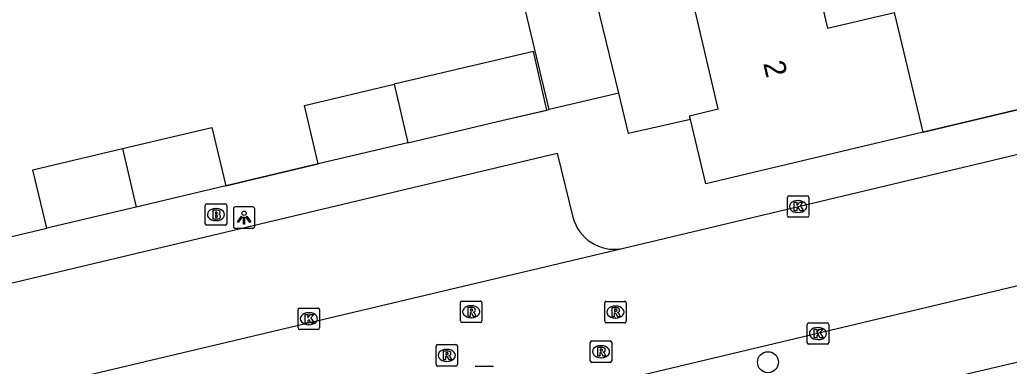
# Model space of a CAD drawing. Extents: x 158038 to 159242, y 380133 to 381214.
# Drawn here: x 158594.98 to 158641.12, y 380505 to 380521.13 of the extents above; entities that cross this region are included whole.
import ezdxf

# ---------------------------------------------------------------- set-up
doc = ezdxf.new("R2010")
doc.units = 0
for name, color, linetype in [('IMGEO_Boom', 7, 'Continuous'), ('IMGEO_Brandkraan', 7, 'Continuous'), ('IMGEO_Hek', 7, 'Continuous'), ('IMGEO_Kolk', 7, 'Continuous'), ('IMGEO_Lichtpunt', 7, 'Continuous'), ('IMGEO_Muur', 7, 'Continuous'), ('IMGEO_Pand', 7, 'Continuous'), ('IMGEO_Pand_nummerreeks', 7, 'Continuous'), ('IMGEO_Rijbaan_lokaal_open', 7, 'Continuous'), ('IMGEO_Rioolput', 7, 'Continuous'), ('IMGEO_Voetpad_open', 7, 'Continuous')]:
    doc.layers.add(name, color=color, linetype=linetype)

msp = doc.modelspace()

# ---------------------------------------------------------------- linework, layer by layer
at = {"layer": 'IMGEO_Boom'}
msp.add_circle((158629.869, 380505.187), 0.489, dxfattribs=at)
at = {"layer": 'IMGEO_Brandkraan'}
for p, q in [((158603.628, 380511.636), (158603.628, 380512.488)), ((158603.703, 380512.562), (158604.555, 380512.562)), ((158604.629, 380512.488), (158604.629, 380511.636)), ((158604.116, 380512.342), (158604.141, 380512.342)), ((158604.555, 380511.562), (158603.703, 380511.562)), ((158604.139, 380511.782), (158604.114, 380511.782))]:
    msp.add_line(p, q, dxfattribs=at)
for points in [[(158603.628, 380511.636), (158603.628, 380512.488)], [(158603.703, 380512.562), (158604.555, 380512.562)], [(158604.629, 380512.488), (158604.629, 380511.636)], [(158603.976, 380512.262), (158603.976, 380511.862), (158604.189, 380511.862)], [(158604.207, 380512.262), (158603.976, 380512.262)], [(158604.155, 380512.181), (158604.101, 380512.181), (158604.101, 380512.105)], [(158604.101, 380512.105), (158604.154, 380512.105)], [(158604.163, 380512.029), (158604.101, 380512.029), (158604.101, 380511.948)], [(158604.555, 380511.562), (158603.703, 380511.562)], [(158604.101, 380511.948), (158604.163, 380511.948)]]:
    msp.add_lwpolyline(points, dxfattribs=at)
for centre, radius, start, end in [((158603.705, 380512.486), 0.0765, 91.552, 178.448), ((158603.705, 380512.486), 0.0765, 91.552, 178.448), ((158604.553, 380512.486), 0.0765, 1.552, 88.448), ((158604.553, 380512.486), 0.0765, 1.552, 88.448), ((158604.156, 380512.143), 0.0379, 267.8285, 90.9355), ((158604.164, 380511.988), 0.0404, 269.8759, 90.5077), ((158604.211, 380512.117), 0.145, 59.4692, 91.5367), ((158604.236, 380512.164), 0.0922, 285.5137, 58.1501), ((158604.241, 380511.972), 0.105, 301.3115, 78.989), ((158603.705, 380511.638), 0.0765, 181.552, 268.448), ((158603.705, 380511.638), 0.0765, 181.552, 268.448), ((158604.195, 380512.113), 0.251, 268.6676, 293.5347), ((158604.553, 380511.638), 0.0765, 271.552, 358.448), ((158604.553, 380511.638), 0.0765, 271.552, 358.448)]:
    msp.add_arc(centre, radius, start, end, dxfattribs=at)
for centre, major_axis, ratio, start_param, end_param in [((158604.115, 380512.062), (-0.387, 0.002), 0.722429, 4.712389, 7.853982), ((158604.14, 380512.062), (-0.39, 0.002), 0.717154, 1.570796, 4.712389)]:
    msp.add_ellipse(centre, major_axis=major_axis, ratio=ratio, start_param=start_param, end_param=end_param, dxfattribs=at)
at = {"layer": 'IMGEO_Hek'}
for points in [[(158637.101, 380515.894), (158657.23, 380520.681)], [(158608.894, 380514.423), (158604.583, 380513.396)]]:
    msp.add_lwpolyline(points, dxfattribs=at)
at = {"layer": 'IMGEO_Kolk'}
for p, q in [((158630.848, 380512.937), (158631.7, 380512.937)), ((158630.773, 380512.011), (158630.773, 380512.863)), ((158631.261, 380512.717), (158631.286, 380512.717)), ((158631.774, 380512.863), (158631.774, 380512.011)), ((158631.284, 380512.157), (158631.259, 380512.157)), ((158631.7, 380511.937), (158630.848, 380511.937)), ((158607.961, 380506.784), (158607.961, 380507.636)), ((158608.036, 380507.71), (158608.888, 380507.71)), ((158608.449, 380507.49), (158608.474, 380507.49)), ((158608.962, 380507.636), (158608.962, 380506.784)), ((158631.698, 380506.095), (158631.698, 380506.947)), ((158631.773, 380507.021), (158632.625, 380507.021)), ((158632.699, 380506.947), (158632.699, 380506.095)), ((158608.888, 380506.71), (158608.036, 380506.71)), ((158608.472, 380506.93), (158608.447, 380506.93)), ((158632.186, 380506.801), (158632.211, 380506.801)), ((158632.625, 380506.021), (158631.773, 380506.021)), ((158632.209, 380506.241), (158632.184, 380506.241))]:
    msp.add_line(p, q, dxfattribs=at)
for points in [[(158630.848, 380512.937), (158631.7, 380512.937)], [(158630.773, 380512.011), (158630.773, 380512.863)], [(158631.094, 380512.637), (158631.217, 380512.637), (158631.217, 380512.486), (158631.347, 380512.637), (158631.511, 380512.637), (158631.365, 380512.486), (158631.518, 380512.237), (158631.366, 380512.237), (158631.281, 380512.401), (158631.217, 380512.334), (158631.217, 380512.237), (158631.094, 380512.237), (158631.094, 380512.637)], [(158631.774, 380512.863), (158631.774, 380512.011)], [(158631.7, 380511.937), (158630.848, 380511.937)], [(158607.961, 380506.784), (158607.961, 380507.636)], [(158608.036, 380507.71), (158608.888, 380507.71)], [(158608.282, 380507.41), (158608.405, 380507.41), (158608.405, 380507.259), (158608.535, 380507.41), (158608.699, 380507.41), (158608.553, 380507.259), (158608.706, 380507.01), (158608.554, 380507.01), (158608.469, 380507.174), (158608.405, 380507.107), (158608.405, 380507.01), (158608.282, 380507.01), (158608.282, 380507.41)], [(158608.962, 380507.636), (158608.962, 380506.784)], [(158631.698, 380506.095), (158631.698, 380506.947)], [(158631.773, 380507.021), (158632.625, 380507.021)], [(158632.699, 380506.947), (158632.699, 380506.095)], [(158608.888, 380506.71), (158608.036, 380506.71)], [(158632.019, 380506.721), (158632.142, 380506.721), (158632.142, 380506.57), (158632.272, 380506.721), (158632.436, 380506.721), (158632.29, 380506.57), (158632.443, 380506.321), (158632.291, 380506.321), (158632.206, 380506.485), (158632.142, 380506.418), (158632.142, 380506.321), (158632.019, 380506.321), (158632.019, 380506.721)], [(158632.625, 380506.021), (158631.773, 380506.021)]]:
    msp.add_lwpolyline(points, dxfattribs=at)
for centre, start, end in [((158630.85, 380512.861), 91.552, 178.448), ((158630.85, 380512.861), 91.552, 178.448), ((158631.698, 380512.861), 1.552, 88.448), ((158631.698, 380512.861), 1.552, 88.448), ((158630.85, 380512.013), 181.552, 268.448), ((158630.85, 380512.013), 181.552, 268.448), ((158631.698, 380512.013), 271.552, 358.448), ((158631.698, 380512.013), 271.552, 358.448), ((158608.038, 380507.634), 91.552, 178.448), ((158608.038, 380507.634), 91.552, 178.448), ((158608.886, 380507.634), 1.552, 88.448), ((158608.886, 380507.634), 1.552, 88.448), ((158631.775, 380506.945), 91.552, 178.448), ((158631.775, 380506.945), 91.552, 178.448), ((158632.623, 380506.945), 1.552, 88.448), ((158632.623, 380506.945), 1.552, 88.448), ((158608.038, 380506.786), 181.552, 268.448), ((158608.038, 380506.786), 181.552, 268.448), ((158608.886, 380506.786), 271.552, 358.448), ((158608.886, 380506.786), 271.552, 358.448), ((158631.775, 380506.097), 181.552, 268.448), ((158631.775, 380506.097), 181.552, 268.448), ((158632.623, 380506.097), 271.552, 358.448), ((158632.623, 380506.097), 271.552, 358.448)]:
    msp.add_arc(centre, 0.0765, start, end, dxfattribs=at)
for centre, major_axis, ratio, start_param, end_param in [((158631.26, 380512.437), (-0.387, 0.002), 0.722429, 4.712389, 7.853982), ((158631.285, 380512.437), (-0.39, 0.002), 0.717154, 1.570796, 4.712389), ((158608.448, 380507.21), (-0.387, 0.002), 0.722429, 4.712389, 7.853982), ((158608.473, 380507.21), (-0.39, 0.002), 0.717154, 1.570796, 4.712389), ((158632.185, 380506.521), (-0.387, 0.002), 0.722429, 4.712389, 7.853982), ((158632.21, 380506.521), (-0.39, 0.002), 0.717154, 1.570796, 4.712389)]:
    msp.add_ellipse(centre, major_axis=major_axis, ratio=ratio, start_param=start_param, end_param=end_param, dxfattribs=at)
at = {"layer": 'IMGEO_Lichtpunt'}
for p, q in [((158604.939, 380512.326), (158604.939, 380511.519)), ((158604.939, 380512.326), (158604.939, 380511.519)), ((158605.841, 380512.421), (158605.033, 380512.421)), ((158605.841, 380512.421), (158605.033, 380512.421)), ((158605.935, 380511.519), (158605.935, 380512.326)), ((158605.935, 380511.519), (158605.935, 380512.326)), ((158605.033, 380511.425), (158605.841, 380511.425)), ((158605.033, 380511.425), (158605.841, 380511.425))]:
    msp.add_line(p, q, dxfattribs=at)
for points in [[(158605.313, 380511.99), (158605.352, 380511.962), (158605.164, 380511.7), (158605.126, 380511.727), (158605.313, 380511.99)], [(158605.415, 380511.942), (158605.462, 380511.942), (158605.462, 380511.62), (158605.415, 380511.62), (158605.415, 380511.942)], [(158605.525, 380511.962), (158605.563, 380511.989), (158605.75, 380511.727), (158605.711, 380511.699), (158605.525, 380511.962)]]:
    msp.add_lwpolyline(points, dxfattribs=at)
msp.add_circle((158605.438, 380512.124), 0.0994, dxfattribs=at)
for centre, start, end in [((158605.033, 380512.326), 90, 180), ((158605.033, 380512.326), 90, 180), ((158605.841, 380512.326), 0, 90), ((158605.841, 380512.326), 0, 90), ((158605.033, 380511.519), 180, 270), ((158605.033, 380511.519), 180, 270), ((158605.841, 380511.519), 270, 0), ((158605.841, 380511.519), 270, 360)]:
    msp.add_arc(centre, 0.0946, start, end, dxfattribs=at)
at = {"layer": 'IMGEO_Muur'}
msp.add_lwpolyline([(158617.262, 380516.389), (158619.67, 380516.952), (158617.202, 380527.238)], dxfattribs=at)
at = {"layer": 'IMGEO_Pand'}
for points in [[(158628.951, 380523.136), (158631.919, 380523.838), (158632.651, 380520.742), (158635.772, 380521.48)], [(158626.253, 380516.497), (158626.212, 380516.665), (158627.553, 380516.986), (158626.249, 380522.497), (158628.951, 380523.136)], [(158637.101, 380515.894), (158635.772, 380521.48)], [(158619.56, 380516.926), (158618.928, 380519.663), (158616.621, 380519.115), (158612.437, 380518.132)], [(158608.894, 380514.423), (158608.253, 380517.149), (158612.437, 380518.132)], [(158612.437, 380518.132), (158613.078, 380515.406)], [(158613.078, 380515.406), (158617.262, 380516.389), (158619.56, 380516.926)], [(158637.101, 380515.894), (158626.973, 380513.486), (158626.253, 380516.497)], [(158599.765, 380515.134), (158603.939, 380516.121), (158604.583, 380513.396)], [(158613.078, 380515.406), (158608.894, 380514.423)], [(158596.234, 380511.423), (158595.59, 380514.148), (158599.765, 380515.134)], [(158599.765, 380515.134), (158600.409, 380512.41)], [(158604.583, 380513.396), (158600.409, 380512.41)], [(158600.409, 380512.41), (158596.234, 380511.423)]]:
    msp.add_lwpolyline(points, dxfattribs=at)
at = {"layer": 'IMGEO_Rijbaan_lokaal_open'}
for points in [[(158623.075, 380510.483), (158649.95, 380516.879)], [(158651.329, 380511.074), (158621.203, 380503.911), (158617.159, 380502.945)], [(158580.936, 380500.512), (158623.075, 380510.483)]]:
    msp.add_lwpolyline(points, dxfattribs=at)
at = {"layer": 'IMGEO_Rioolput'}
for p, q in [((158615.529, 380507.109), (158615.529, 380507.961)), ((158615.604, 380508.035), (158616.456, 380508.035)), ((158616.53, 380507.961), (158616.53, 380507.109)), ((158622.256, 380507.095), (158622.256, 380507.947)), ((158622.331, 380508.021), (158623.183, 380508.021)), ((158623.257, 380507.947), (158623.257, 380507.095)), ((158616.017, 380507.815), (158616.042, 380507.815)), ((158622.744, 380507.801), (158622.769, 380507.801)), ((158616.456, 380507.035), (158615.604, 380507.035)), ((158616.04, 380507.255), (158616.015, 380507.255)), ((158623.183, 380507.021), (158622.331, 380507.021)), ((158622.767, 380507.241), (158622.742, 380507.241)), ((158621.584, 380505.25), (158621.584, 380506.102)), ((158621.659, 380506.176), (158622.511, 380506.176)), ((158622.585, 380506.102), (158622.585, 380505.25)), ((158614.39, 380505.079), (158614.39, 380505.931)), ((158614.465, 380506.005), (158615.317, 380506.005)), ((158614.878, 380505.785), (158614.903, 380505.785)), ((158615.391, 380505.931), (158615.391, 380505.079)), ((158622.072, 380505.956), (158622.097, 380505.956)), ((158614.901, 380505.225), (158614.876, 380505.225)), ((158622.511, 380505.176), (158621.659, 380505.176)), ((158622.095, 380505.396), (158622.07, 380505.396)), ((158615.317, 380505.005), (158614.465, 380505.005)), ((158616.221, 380505), (158617.073, 380505))]:
    msp.add_line(p, q, dxfattribs=at)
for points in [[(158615.529, 380507.109), (158615.529, 380507.961)], [(158615.604, 380508.035), (158616.456, 380508.035)], [(158616.53, 380507.961), (158616.53, 380507.109)], [(158622.256, 380507.095), (158622.256, 380507.947)], [(158622.331, 380508.021), (158623.183, 380508.021)], [(158623.257, 380507.947), (158623.257, 380507.095)], [(158616.118, 380507.733), (158615.866, 380507.735), (158615.866, 380507.335)], [(158615.866, 380507.335), (158615.99, 380507.335), (158615.99, 380507.497), (158616.001, 380507.497)], [(158616.044, 380507.654), (158615.99, 380507.654), (158615.99, 380507.573)], [(158615.99, 380507.573), (158616.042, 380507.573)], [(158616.048, 380507.468), (158616.119, 380507.335), (158616.259, 380507.335), (158616.194, 380507.461)], [(158622.845, 380507.719), (158622.593, 380507.721), (158622.593, 380507.321)], [(158622.593, 380507.321), (158622.717, 380507.321), (158622.717, 380507.483), (158622.728, 380507.483)], [(158622.771, 380507.64), (158622.717, 380507.64), (158622.717, 380507.559)], [(158622.717, 380507.559), (158622.769, 380507.559)], [(158622.775, 380507.454), (158622.846, 380507.321), (158622.986, 380507.321), (158622.921, 380507.447)], [(158616.456, 380507.035), (158615.604, 380507.035)], [(158623.183, 380507.021), (158622.331, 380507.021)], [(158621.584, 380505.25), (158621.584, 380506.102)], [(158621.659, 380506.176), (158622.511, 380506.176)], [(158622.585, 380506.102), (158622.585, 380505.25)], [(158614.39, 380505.079), (158614.39, 380505.931)], [(158614.465, 380506.005), (158615.317, 380506.005)], [(158614.979, 380505.703), (158614.727, 380505.705), (158614.727, 380505.305)], [(158614.905, 380505.624), (158614.851, 380505.624), (158614.851, 380505.543)], [(158615.391, 380505.931), (158615.391, 380505.079)], [(158622.173, 380505.874), (158621.921, 380505.876), (158621.921, 380505.476)], [(158621.921, 380505.476), (158622.045, 380505.476), (158622.045, 380505.638), (158622.056, 380505.638)], [(158622.099, 380505.795), (158622.045, 380505.795), (158622.045, 380505.714)], [(158622.045, 380505.714), (158622.097, 380505.714)], [(158622.103, 380505.609), (158622.174, 380505.476), (158622.314, 380505.476), (158622.249, 380505.602)], [(158614.727, 380505.305), (158614.851, 380505.305), (158614.851, 380505.467), (158614.862, 380505.467)], [(158614.851, 380505.543), (158614.903, 380505.543)], [(158614.909, 380505.438), (158614.98, 380505.305), (158615.12, 380505.305), (158615.055, 380505.431)], [(158622.511, 380505.176), (158621.659, 380505.176)], [(158615.317, 380505.005), (158614.465, 380505.005)], [(158616.221, 380505), (158617.073, 380505)]]:
    msp.add_lwpolyline(points, dxfattribs=at)
for centre, radius, start, end in [((158615.606, 380507.959), 0.0765, 91.552, 178.448), ((158615.606, 380507.959), 0.0765, 91.552, 178.448), ((158616.454, 380507.959), 0.0765, 1.552, 88.448), ((158616.454, 380507.959), 0.0765, 1.552, 88.448), ((158622.333, 380507.945), 0.0765, 91.552, 178.448), ((158622.333, 380507.945), 0.0765, 91.552, 178.448), ((158623.181, 380507.945), 0.0765, 1.552, 88.448), ((158623.181, 380507.945), 0.0765, 1.552, 88.448), ((158616, 380507.444), 0.0533, 26.0293, 88.6989), ((158616.026, 380507.762), 0.19, 274.7715, 282.9687), ((158616.05, 380507.558), 0.0964, 77.0061, 93.1865), ((158616.064, 380507.615), 0.0378, 276.6634, 79.6772), ((158616.117, 380507.623), 0.109, 350.3612, 89.416), ((158616.115, 380507.623), 0.112, 277.5842, 350.9817), ((158616.099, 380507.408), 0.108, 29.5134, 73.7905), ((158622.727, 380507.43), 0.0533, 26.0293, 88.6989), ((158622.753, 380507.748), 0.19, 274.7715, 282.9687), ((158622.777, 380507.544), 0.0964, 77.0061, 93.1865), ((158622.791, 380507.601), 0.0378, 276.6634, 79.6772), ((158622.844, 380507.609), 0.109, 350.3612, 89.416), ((158622.842, 380507.609), 0.112, 277.5842, 350.9817), ((158622.826, 380507.394), 0.108, 29.5134, 73.7905), ((158615.606, 380507.111), 0.0765, 181.552, 268.448), ((158615.606, 380507.111), 0.0765, 181.552, 268.448), ((158616.454, 380507.111), 0.0765, 271.552, 358.448), ((158616.454, 380507.111), 0.0765, 271.552, 358.448), ((158622.333, 380507.097), 0.0765, 181.552, 268.448), ((158622.333, 380507.097), 0.0765, 181.552, 268.448), ((158623.181, 380507.097), 0.0765, 271.552, 358.448), ((158623.181, 380507.097), 0.0765, 271.552, 358.448), ((158621.661, 380506.1), 0.0765, 91.552, 178.448), ((158621.661, 380506.1), 0.0765, 91.552, 178.448), ((158622.509, 380506.1), 0.0765, 1.552, 88.448), ((158622.509, 380506.1), 0.0765, 1.552, 88.448), ((158614.467, 380505.929), 0.0765, 91.552, 178.448), ((158614.467, 380505.929), 0.0765, 91.552, 178.448), ((158614.911, 380505.528), 0.0964, 77.0061, 93.1865), ((158614.925, 380505.585), 0.0378, 276.6634, 79.6772), ((158614.978, 380505.593), 0.109, 350.3612, 89.416), ((158614.976, 380505.593), 0.112, 277.5842, 350.9817), ((158615.315, 380505.929), 0.0765, 1.552, 88.448), ((158615.315, 380505.929), 0.0765, 1.552, 88.448), ((158622.055, 380505.585), 0.0533, 26.0293, 88.6989), ((158622.081, 380505.903), 0.19, 274.7715, 282.9687), ((158622.105, 380505.699), 0.0964, 77.0061, 93.1865), ((158622.119, 380505.756), 0.0378, 276.6634, 79.6772), ((158622.172, 380505.764), 0.109, 350.3612, 89.416), ((158622.17, 380505.764), 0.112, 277.5842, 350.9817), ((158622.154, 380505.549), 0.108, 29.5134, 73.7905), ((158614.861, 380505.414), 0.0533, 26.0293, 88.6989), ((158614.887, 380505.732), 0.19, 274.7715, 282.9687), ((158614.96, 380505.378), 0.108, 29.5134, 73.7905), ((158621.661, 380505.252), 0.0765, 181.552, 268.448), ((158621.661, 380505.252), 0.0765, 181.552, 268.448), ((158622.509, 380505.252), 0.0765, 271.552, 358.448), ((158622.509, 380505.252), 0.0765, 271.552, 358.448), ((158614.467, 380505.081), 0.0765, 181.552, 268.448), ((158614.467, 380505.081), 0.0765, 181.552, 268.448), ((158615.315, 380505.081), 0.0765, 271.552, 358.448), ((158615.315, 380505.081), 0.0765, 271.552, 358.448)]:
    msp.add_arc(centre, radius, start, end, dxfattribs=at)
for centre, major_axis, ratio, start_param, end_param in [((158616.016, 380507.535), (-0.387, 0.002), 0.722429, 4.712389, 7.853982), ((158616.041, 380507.535), (-0.39, 0.002), 0.717154, 1.570796, 4.712389), ((158622.743, 380507.521), (-0.387, 0.002), 0.722429, 4.712389, 7.853982), ((158622.768, 380507.521), (-0.39, 0.002), 0.717154, 1.570796, 4.712389), ((158614.877, 380505.505), (-0.387, 0.002), 0.722429, 4.712389, 7.853982), ((158614.902, 380505.505), (-0.39, 0.002), 0.717154, 1.570796, 4.712389), ((158622.071, 380505.676), (-0.387, 0.002), 0.722429, 4.712389, 7.853982), ((158622.096, 380505.676), (-0.39, 0.002), 0.717154, 1.570796, 4.712389)]:
    msp.add_ellipse(centre, major_axis=major_axis, ratio=ratio, start_param=start_param, end_param=end_param, dxfattribs=at)
at = {"layer": 'IMGEO_Voetpad_open'}
for points in [[(158619.67, 380516.952), (158617.202, 380527.238)], [(158622.907, 380517.709), (158621.736, 380522.581)], [(158657.23, 380520.681), (158637.101, 380515.894)], [(158622.907, 380517.709), (158619.67, 380516.952)], [(158626.253, 380516.497), (158623.359, 380515.831), (158622.907, 380517.709)], [(158619.56, 380516.926), (158619.67, 380516.952)], [(158582.453, 380502.891), (158581.739, 380505.83), (158620.043, 380514.915), (158620.771, 380511.94)], [(158604.583, 380513.396), (158608.894, 380514.423)], [(158591.902, 380510.399), (158596.234, 380511.423)], [(158636.06, 380503.911), (158655.623, 380508.533)]]:
    msp.add_lwpolyline(points, dxfattribs=at)
msp.add_arc((158622.698, 380512.436), 1.989, 194.4456, 280.9376, dxfattribs=at)

# ---------------------------------------------------------------- texts
at = {"layer": 'IMGEO_Pand_nummerreeks'}
msp.add_text('2', height=1, rotation=283.311, dxfattribs=at).set_placement((158629.641, 380519.106))

doc.saveas('drawing.dxf')
